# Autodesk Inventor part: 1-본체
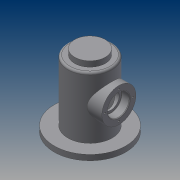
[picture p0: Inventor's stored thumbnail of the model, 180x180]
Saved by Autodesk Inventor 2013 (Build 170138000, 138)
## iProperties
Created: 2014-12
Part Number: 1-본체
Material: Generic
Document SubType Name: Modeling
Designer: SD
Density: 1 g/cm^3
Author: SD
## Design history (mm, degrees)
sketch "스케치1"
  geometry: C1 r 32.5 at (0, 0); C2 r 52.5 at (0, 0); 1 further point
  constraints: 2 centre point, 2 coincident
  dimensions: "d0" = 65 diameter of C1; "d1" = 105 diameter of C2
extrude "돌출1" new body sketch "스케치1" distance "d3" = 98; taper "d4" = 0 deg
fillet "모깎기1" dims "d5" = 3
feature "쉘1" dims "d6" = 5
extrude "돌출2" join sketch "스케치1" distance "d7" = 8; taper "d8" = 0 deg
sketch "스케치2"
  geometry: C1 r 22.5 at (0, 0); 1 further point
  constraints: 1 centre point, 1 coincident
  dimensions: "d9" = 45 diameter of C1
extrude "돌출3" join sketch "스케치2" distance "d10" = 8; taper "d11" = 0 deg
node "작업 평면1"
node "작업 평면2"
sketch "스케치5"
  geometry: L1 (-52.5, 0)-(52.5, 0) reference; C1 r 25 at (0, 55); 1 further point
  constraints: 1 centre point, 1 vertical alignment
  dimensions: "d14" = 50 diameter of C1; "d15" = 55 distance from line of L1 C1.centre
extrude "돌출4" join sketch "스케치5" stored distance "d16" = 8; taper "d17" = 0 deg
hole "구멍1" diameter "d20" = 25; stored, may be unused: countersink angle "d24" = 90 deg, drill point angle "d26" = 0 deg; dims "d18" = 10, "d19" = 10, "d21" = 6, "d22" = 32, "d23" = 12, "d25" = 42.5
fillet "모깎기2" dims "d27" = 1
sketch "스케치6"
  geometry: C1 r 25 at (0, 0) reference; C2 r 17 at (0, 0) reference; 2 further points
  constraints: 1 horizontal alignment
  dimensions: "d28" = 20.5 distance of point (-20.5, 0) C1.centre
hole "구멍2" sketch "스케치6" at (-20.5, 0) diameter "d29" = 2.459; stored, may be unused: countersink angle "d33" = 90 deg, drill point angle "d35" = 118 deg; dims "d30" = 6, "d31" = 32, "d32" = 12, "d34" = 8
fillet "모깎기3" dims "d39" = 0.3
node "솔리드1"
pattern_circular "원형 패턴1" dims angle "d37" = 360 deg
node "투영된 루프1"
other parameters: "d12" = 55, "d13" = 42.5
